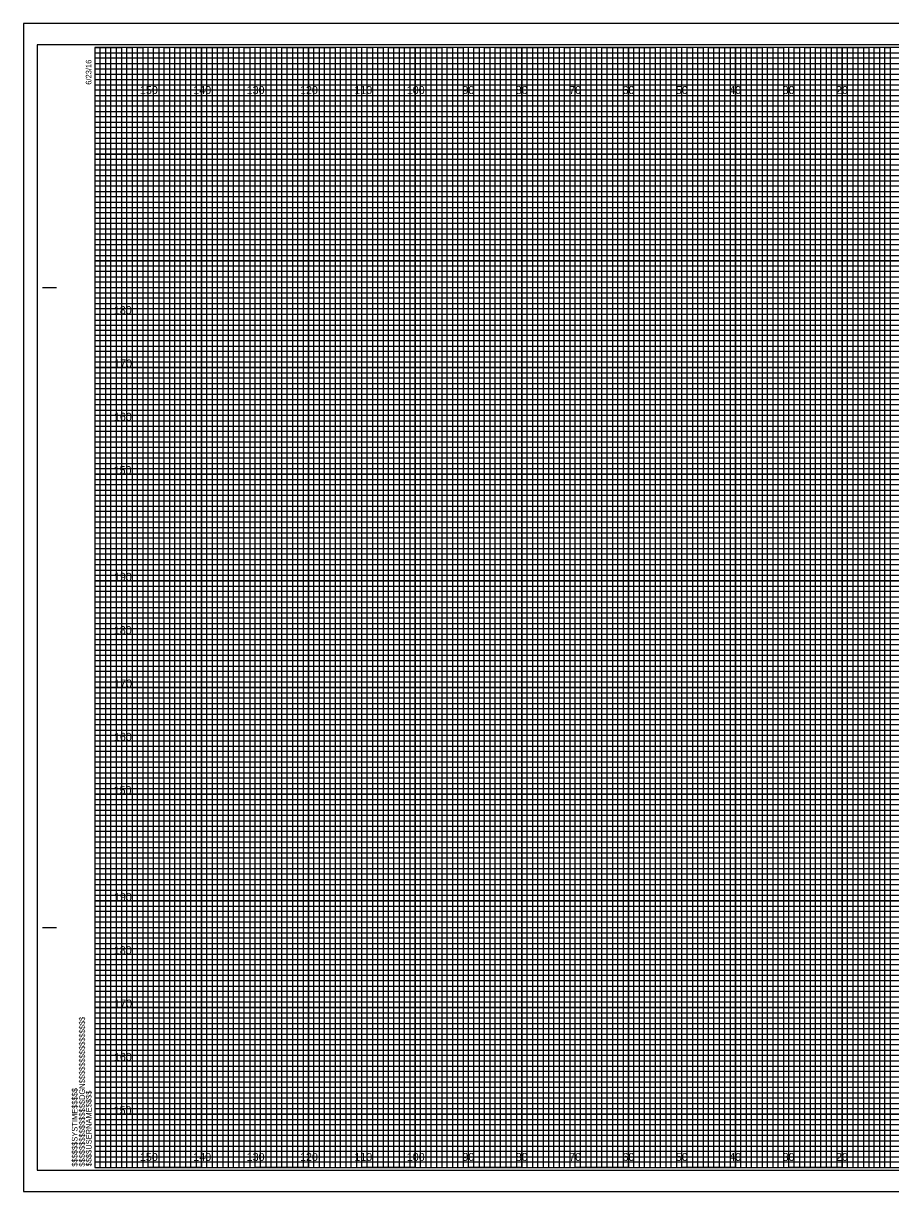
# Model space of a CAD drawing. Extents: x -13 to 323, y -5 to 434.
# Drawn here: x -13.4 to 149.1, y -4.5 to 214.5 of the extents above; entities that cross this region are included whole.
import ezdxf

# ---------------------------------------------------------------- set-up
doc = ezdxf.new("R2010")
doc.units = 0
for name, color, linetype in [('Exist Cross Section Cell', 7, 'Continuous'), ('Exist XS Center Line Elevation Label', 7, 'Continuous'), ('Exist XS Ground Line', 7, 'Continuous'), ('Prop CMT Pvmt Course 1', 7, 'Continuous'), ('Prop CMT Pvmt Course 2', 7, 'Continuous'), ('Prop CMT Pvmt Course 3', 7, 'Continuous'), ('Prop CMT Shld Paved Course 1', 7, 'Continuous'), ('Prop CMT Shld Paved Course 2', 7, 'Continuous'), ('Prop CMT Subgrade Earthwork', 7, 'Continuous'), ('Prop XS Ditch Standard Text', 7, 'Continuous'), ('Scratch_Level_0', 7, 'Continuous')]:
    doc.layers.add(name, color=color, linetype=linetype)

msp = doc.modelspace()

# ---------------------------------------------------------------- linework, layer by layer
at = {"layer": 'Exist XS Center Line Elevation Label'}
for points in [[(0, 210), (5, 210), (5, 0), (15, 0), (15, 210), (25, 210), (25, 0), (35, 0), (35, 210), (45, 210), (45, 0), (55, 0), (55, 210), (65, 210), (65, 0), (75, 0), (75, 210), (85, 210), (85, 0), (95, 0), (95, 210), (105, 210), (105, 0), (115, 0), (115, 210), (125, 210), (125, 0), (135, 0), (135, 210), (145, 210), (145, 0), (155, 0)], [(0, 205), (275, 205)], [(0, 185), (320, 185), (320, 195), (0, 195)], [(0, 165), (320, 165), (320, 175), (0, 175)], [(0, 145), (320, 145), (320, 155), (0, 155)], [(0, 125), (320, 125), (320, 135), (0, 135)], [(0, 105), (320, 105), (320, 115), (0, 115)], [(0, 85), (320, 85), (320, 95), (0, 95)], [(0, 65), (320, 65), (320, 75), (0, 75)], [(0, 45), (320, 45), (320, 55), (0, 55)], [(0, 25), (320, 25), (320, 35), (0, 35)], [(0, 5), (320, 5), (320, 15), (0, 15)]]:
    msp.add_lwpolyline(points, dxfattribs=at)
at = {"layer": 'Exist XS Ground Line'}
for p, q in [((10, 210), (0, 210)), ((10, 0), (10, 210)), ((30, 210), (20, 210)), ((20, 210), (20, 0)), ((30, 0), (30, 210)), ((50, 210), (40, 210)), ((40, 210), (40, 0)), ((50, 0), (50, 210)), ((70, 210), (60, 210)), ((60, 210), (60, 0)), ((70, 0), (70, 210)), ((90, 210), (80, 210)), ((80, 210), (80, 0)), ((90, 0), (90, 210)), ((110, 210), (100, 210)), ((100, 210), (100, 0)), ((110, 0), (110, 210)), ((130, 210), (120, 210)), ((120, 210), (120, 0)), ((130, 0), (130, 210)), ((150, 210), (140, 210)), ((140, 210), (140, 0)), ((20, 0), (10, 0)), ((40, 0), (30, 0)), ((60, 0), (50, 0)), ((80, 0), (70, 0)), ((100, 0), (90, 0)), ((120, 0), (110, 0)), ((140, 0), (130, 0))]:
    msp.add_line(p, q, dxfattribs=at)
for points in [[(0, 200), (320, 200), (320, 190), (0, 190)], [(0, 180), (320, 180), (320, 170), (0, 170)], [(0, 160), (320, 160), (320, 150), (0, 150)], [(0, 140), (320, 140), (320, 130), (0, 130)], [(0, 120), (320, 120), (320, 110), (0, 110)], [(0, 100), (320, 100), (320, 90), (0, 90)], [(0, 80), (320, 80), (320, 70), (0, 70)], [(0, 60), (320, 60), (320, 50), (0, 50)], [(0, 40), (320, 40), (320, 30), (0, 30)], [(0, 20), (320, 20), (320, 10), (0, 10)]]:
    msp.add_lwpolyline(points, dxfattribs=at)
at = {"layer": 'Prop CMT Pvmt Course 1'}
for p, q in [((323.3, 214.5), (-13.4, 214.5)), ((-13.4, 214.5), (-13.4, -4.5)), ((-13.4, -4.5), (323.3, -4.5))]:
    msp.add_line(p, q, dxfattribs=at)
at = {"layer": 'Prop CMT Pvmt Course 2'}
msp.add_lwpolyline([(-13.4, -4.5), (323.3, -4.5), (323.3, 214.5), (-13.4, 214.5)], close=True, dxfattribs=at)
at = {"layer": 'Prop CMT Pvmt Course 3'}
msp.add_lwpolyline([(-10.8, -0.5), (322.4, -0.5), (322.4, 210.5), (-10.8, 210.5)], close=True, dxfattribs=at)
at = {"layer": 'Prop CMT Shld Paved Course 1'}
for p, q in [((-9.8, 165), (-7.3, 165)), ((-9.7, 165), (-7.2, 165)), ((-9.8, 45), (-7.3, 45)), ((-9.7, 45), (-7.2, 45)), ((0, 0), (0, 0)), ((0, 0), (0, 0)), ((0, 0), (0, 0)), ((0, 0), (0, 0)), ((0, 0), (0, 0)), ((0, 0), (0, 0)), ((0, 0), (0, 0))]:
    msp.add_line(p, q, dxfattribs=at)
msp.add_lwpolyline([(320, 210), (0, 210), (0, 0), (320, 0)], close=True, dxfattribs=at)
at = {"layer": 'Prop CMT Shld Paved Course 2'}
for points in [[(0, 0), (1, 0), (1, 210), (2, 210), (2, 0)], [(2, 0), (3, 0), (3, 210), (4, 210), (4, 0)], [(5, 0), (6, 0), (6, 210), (7, 210), (7, 0)], [(7, 0), (8, 0), (8, 210), (9, 210), (9, 0)], [(10, 0), (11, 0), (11, 210), (12, 210), (12, 0)], [(12, 0), (13, 0), (13, 210), (14, 210), (14, 0)], [(15, 0), (16, 0), (16, 210), (17, 210), (17, 0)], [(17, 0), (18, 0), (18, 210), (19, 210), (19, 0)], [(20, 0), (21, 0), (21, 210), (22, 210), (22, 0)], [(22, 0), (23, 0), (23, 210), (24, 210), (24, 0)], [(25, 0), (26, 0), (26, 210), (27, 210), (27, 0)], [(27, 0), (28, 0), (28, 210), (29, 210), (29, 0)], [(30, 0), (31, 0), (31, 210), (32, 210), (32, 0)], [(32, 0), (33, 0), (33, 210), (34, 210), (34, 0)], [(35, 0), (36, 0), (36, 210), (37, 210), (37, 0)], [(37, 0), (38, 0), (38, 210), (39, 210), (39, 0)], [(40, 0), (41, 0), (41, 210), (42, 210), (42, 0)], [(42, 0), (43, 0), (43, 210), (44, 210), (44, 0)], [(45, 0), (46, 0), (46, 210), (47, 210), (47, 0)], [(47, 0), (48, 0), (48, 210), (49, 210), (49, 0)], [(50, 0), (51, 0), (51, 210), (52, 210), (52, 0)], [(52, 0), (53, 0), (53, 210), (54, 210), (54, 0)], [(55, 0), (56, 0), (56, 210), (57, 210), (57, 0)], [(57, 0), (58, 0), (58, 210), (59, 210), (59, 0)], [(60, 0), (61, 0), (61, 210), (62, 210), (62, 0)], [(62, 0), (63, 0), (63, 210), (64, 210), (64, 0)], [(65, 0), (66, 0), (66, 210), (67, 210), (67, 0)], [(67, 0), (68, 0), (68, 210), (69, 210), (69, 0)], [(70, 0), (71, 0), (71, 210), (72, 210), (72, 0)], [(72, 0), (73, 0), (73, 210), (74, 210), (74, 0)], [(75, 0), (76, 0), (76, 210), (77, 210), (77, 0)], [(77, 0), (78, 0), (78, 210), (79, 210), (79, 0)], [(80, 0), (81, 0), (81, 210), (82, 210), (82, 0)], [(82, 0), (83, 0), (83, 210), (84, 210), (84, 0)], [(85, 0), (86, 0), (86, 210), (87, 210), (87, 0)], [(87, 0), (88, 0), (88, 210), (89, 210), (89, 0)], [(90, 0), (91, 0), (91, 210), (92, 210), (92, 0)], [(92, 0), (93, 0), (93, 210), (94, 210), (94, 0)], [(95, 0), (96, 0), (96, 210), (97, 210), (97, 0)], [(97, 0), (98, 0), (98, 210), (99, 210), (99, 0)], [(100, 0), (101, 0), (101, 210), (102, 210), (102, 0)], [(102, 0), (103, 0), (103, 210), (104, 210), (104, 0)], [(105, 0), (106, 0), (106, 210), (107, 210), (107, 0)], [(107, 0), (108, 0), (108, 210), (109, 210), (109, 0)], [(110, 0), (111, 0), (111, 210), (112, 210), (112, 0)], [(112, 0), (113, 0), (113, 210), (114, 210), (114, 0)], [(115, 0), (116, 0), (116, 210), (117, 210), (117, 0)], [(117, 0), (118, 0), (118, 210), (119, 210), (119, 0)], [(120, 0), (121, 0), (121, 210), (122, 210), (122, 0)], [(122, 0), (123, 0), (123, 210), (124, 210), (124, 0)], [(125, 0), (126, 0), (126, 210), (127, 210), (127, 0)], [(127, 0), (128, 0), (128, 210), (129, 210), (129, 0)], [(130, 0), (131, 0), (131, 210), (132, 210), (132, 0)], [(132, 0), (133, 0), (133, 210), (134, 210), (134, 0)], [(135, 0), (136, 0), (136, 210), (137, 210), (137, 0)], [(137, 0), (138, 0), (138, 210), (139, 210), (139, 0)], [(140, 0), (141, 0), (141, 210), (142, 210), (142, 0)], [(142, 0), (143, 0), (143, 210), (144, 210), (144, 0)], [(145, 0), (146, 0), (146, 210), (147, 210), (147, 0)], [(147, 0), (148, 0), (148, 210), (149, 210), (149, 0)]]:
    msp.add_lwpolyline(points, dxfattribs=at)
at = {"layer": 'Prop CMT Subgrade Earthwork'}
for p, q in [((10, 0), (10, 210)), ((20, 0), (20, 210)), ((30, 0), (30, 210)), ((40, 0), (40, 210)), ((50, 0), (50, 210)), ((60, 0), (60, 210)), ((70, 0), (70, 210)), ((80, 0), (80, 210)), ((90, 0), (90, 210)), ((100, 0), (100, 210)), ((110, 0), (110, 210)), ((120, 0), (120, 210)), ((130, 0), (130, 210)), ((140, 0), (140, 210)), ((0, 200), (320, 200)), ((0, 190), (320, 190)), ((0, 180), (320, 180)), ((0, 170), (320, 170)), ((0, 160), (320, 160)), ((0, 150), (320, 150)), ((0, 140), (320, 140)), ((0, 130), (320, 130)), ((0, 120), (320, 120)), ((0, 110), (320, 110)), ((0, 100), (320, 100)), ((0, 90), (320, 90)), ((0, 80), (320, 80)), ((0, 70), (320, 70)), ((0, 60), (320, 60)), ((0, 50), (320, 50)), ((0, 40), (320, 40)), ((0, 30), (320, 30)), ((0, 20), (320, 20)), ((0, 10), (320, 10))]:
    msp.add_line(p, q, dxfattribs=at)
at = {"layer": 'Scratch_Level_0'}
for p, q in [((0, 209), (260, 209)), ((260, 207.98), (0, 207.98)), ((0, 207.98), (0, 207)), ((0, 207), (260, 207)), ((260, 205.89), (0, 205.89)), ((0, 205.89), (0, 204)), ((0, 204), (320, 204))]:
    msp.add_line(p, q, dxfattribs=at)
for points in [[(0, 203), (270, 203), (320, 203), (320, 202), (0, 202)], [(0, 201), (320, 201), (320, 199), (0, 199)], [(0, 198), (320, 198), (320, 197), (0, 196.98)], [(0, 196), (320, 196), (320, 194), (0, 194)], [(0, 193), (320, 193), (320, 192), (0, 192)], [(0, 191), (320, 191), (320, 189), (0, 189)], [(0, 188), (320, 188), (320, 187), (0, 187)], [(0, 186), (320, 186), (320, 184), (0, 184)], [(0, 183), (320, 183), (320, 182), (0, 182)], [(0, 181), (320, 181), (320, 179), (0, 179)], [(0, 178), (320, 178), (320, 177), (0, 177)], [(0, 176), (320, 176), (320, 173.95), (320, 173), (320, 172), (0, 172)], [(0, 174), (320, 174), (320, 173), (0, 173)], [(0, 171), (320, 171), (320, 169), (0, 169.03)], [(0, 169.03), (320, 169), (320, 168), (0, 168)], [(0, 167), (320, 167), (320, 166), (0, 166)], [(0, 164), (320, 164), (320, 163), (0, 163)], [(0, 162), (320, 162), (320, 161), (0, 161)], [(-0.07, 158.89), (320, 158.89), (320, 157.88), (-0.07, 157.88)], [(0, 157), (320, 157), (320, 156), (0, 156)], [(0, 154), (320, 154), (320, 153), (0, 153)], [(0, 152), (320, 152), (320, 151), (0, 151)], [(0, 149), (320, 149), (320, 148), (0, 148)], [(0, 147), (320, 147), (320, 146), (0, 146)], [(0, 144), (320, 144), (320, 143), (0, 143)], [(0, 142), (320, 142), (320, 141), (0, 141)], [(0, 139), (320, 139), (319.99, 137.98), (0, 138)], [(0, 137), (320, 137), (320, 136), (0, 136)], [(0, 134), (320, 134), (320, 133), (0, 133)], [(0, 132), (320, 132), (320, 131), (0, 131)], [(0, 129), (320, 129), (320, 128), (0, 128)], [(0, 127), (320, 127), (320, 126), (0, 126)], [(0, 124), (320, 124), (320, 123), (0, 123)], [(0, 122), (320, 122), (320, 121), (0, 121)], [(0, 119), (320, 119), (320, 118), (0, 118)], [(0, 116.99), (320.07, 116.91), (320, 116), (0, 116)], [(0, 114), (320, 114), (320, 113), (0, 113)], [(0, 112), (320, 112), (320, 111), (0, 111)], [(0, 109), (320, 109), (320, 108), (0, 108)], [(0, 107), (320, 107), (320, 106), (0, 106)], [(0, 104), (320, 104), (320, 103), (0, 103)], [(0, 102), (320, 102), (320, 101), (0, 101)], [(0, 99), (320, 99), (320, 98), (0, 98)], [(0, 97), (320, 97), (320, 96), (0, 96)], [(0, 94), (320, 94), (320, 93), (0, 93)], [(0, 92), (320, 92), (320, 91), (0, 91)], [(0, 89), (320, 89), (320, 88), (0, 88)], [(0, 87), (320, 87), (320, 86), (0, 86)], [(0, 84), (320, 84), (320, 83), (0, 83)], [(0, 82), (320, 82), (320, 81), (0, 81)], [(0, 79), (320, 79), (319.99, 77.98), (0, 78)], [(0, 77), (320, 77), (320, 76), (0, 76)], [(0, 74), (320, 74), (320, 73), (0, 73)], [(0, 72), (320, 72), (320, 71), (0, 71)], [(0, 69), (320, 69), (320, 68), (0, 68)], [(0, 67), (320, 67), (320, 66), (0, 66)], [(0, 64), (320, 64), (320, 63), (0, 63)], [(0, 62), (320, 62), (320, 61), (0, 61)], [(0, 59), (320, 59), (320, 58), (0, 58)], [(0, 56.99), (320.07, 56.91), (320, 56), (0, 56)], [(0, 54), (320, 54), (320, 53), (0, 53)], [(0, 52), (320, 52), (320, 51), (0, 51)], [(0, 49), (320, 49), (320, 48), (0, 48)], [(0, 47), (320, 47), (320, 46), (0, 46)], [(0, 44), (320, 44), (320, 43), (0, 43)], [(0, 42), (320, 42), (320, 41), (0, 41)], [(0, 39), (320, 39), (320, 38), (0, 38)], [(0, 37), (320, 37), (320, 36), (0, 36)], [(0, 34), (320, 34), (320, 33), (0, 33)], [(0, 32), (320, 32), (320, 31), (0, 31)], [(0, 29), (320, 29), (320, 28), (0, 28)], [(0, 27), (320, 27), (320, 26), (0, 26)], [(0, 24), (320, 24), (320, 23), (0, 23)], [(0, 22), (320, 22), (320, 21), (0, 21)], [(0, 19), (320, 19), (320, 18), (0, 18)], [(0, 17), (320, 17), (320, 16), (0, 16)], [(0, 14), (320, 14), (320, 13), (0, 13)], [(0, 12), (320, 12), (320, 11), (0, 11)], [(0, 9), (320, 9), (320, 8), (0, 8)], [(0, 7), (320, 7), (320, 6), (0, 6)], [(0, 4), (320, 4), (320, 3), (0, 3)], [(0, 2), (320, 2), (320, 1), (0, 1)]]:
    msp.add_lwpolyline(points, dxfattribs=at)

# ---------------------------------------------------------------- texts
at = {"layer": 'Exist Cross Section Cell'}
for s, p in [('180', (3.55, 160)), ('170', (3.61, 150)), ('160', (3.57, 140)), ('150', (3.52, 130)), ('190', (3.57, 110)), ('180', (3.55, 100)), ('170', (3.61, 90)), ('160', (3.57, 80)), ('150', (3.52, 70)), ('190', (3.57, 50)), ('180', (3.55, 40)), ('170', (3.61, 30)), ('160', (3.57, 20)), ('150', (3.52, 10))]:
    msp.add_text(s, height=1.5, dxfattribs=at).set_placement(p)
at = {"layer": 'Prop CMT Shld Paved Course 1'}
for s, p in [('6/23/16', (-0.65, 203)), ('$$$$$$$$$$$$$$$$DGN$$$$$$$$$$$$$$$$', (-1.88, 0.18)), ('$$$$$$SYSTIME$$$$$', (-3.26, 0.18)), ('$$$$USERNAME$$$$', (-0.62, 0.23))]:
    msp.add_text(s, height=1.05, rotation=90, dxfattribs=at).set_placement(p)
at = {"layer": 'Prop XS Ditch Standard Text'}
for s, p in [('150', (8.44, 201.25)), ('140', (18.44, 201.25)), ('130', (28.44, 201.25)), ('120', (38.44, 201.25)), ('110', (48.62, 201.25)), ('100', (58.44, 201.25)), ('90', (68.86, 201.25)), ('80', (78.86, 201.25)), ('70', (88.86, 201.25)), ('60', (98.86, 201.25)), ('50', (108.86, 201.25)), ('40', (118.86, 201.25)), ('30', (128.86, 201.25)), ('20', (138.86, 201.25)), ('150', (8.44, 1.25)), ('140', (18.44, 1.25)), ('130', (28.44, 1.25)), ('120', (38.44, 1.25)), ('110', (48.62, 1.25)), ('100', (58.44, 1.25)), ('90', (68.86, 1.25)), ('80', (78.86, 1.25)), ('70', (88.86, 1.25)), ('60', (98.86, 1.25)), ('50', (108.86, 1.25)), ('40', (118.86, 1.25)), ('30', (128.86, 1.25)), ('20', (138.86, 1.25))]:
    msp.add_text(s, height=1.5, dxfattribs=at).set_placement(p)

doc.saveas('drawing.dxf')
